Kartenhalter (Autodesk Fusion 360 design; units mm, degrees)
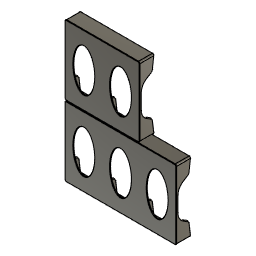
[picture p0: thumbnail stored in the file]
sketch "Skizze1" plane through (0, 0, 0) normal (0, 1, 0) x axis (1, 0, 0)
  line L1 (52, -2) -> (2, -2)
  line L2 (52, -97) -> (52, -2)
  line L3 (2, -97) -> (52, -97)
  line L4 (2, -2) -> (2, -97)
  line L5 (104, -2) -> (54, -2)
  line L6 (104, -97) -> (104, -2)
  line L7 (54, -97) -> (104, -97)
  line L8 (54, -2) -> (54, -97)
  line L9 (156, -2) -> (106, -2)
  line L10 (156, -97) -> (156, -2)
  line L11 (106, -97) -> (156, -97)
  line L12 (106, -2) -> (106, -97)
  line L13 (0, -99) -> (158, -99)
  line L14 (0, 0) -> (0, -99)
  line L15 (158, 0) -> (0, 0)
  line L16 (158, -99) -> (158, 0)
  curve K1 (12, -49.5) -> (42, -49.5)
  curve K2 (27, -79.5) -> (27, -19.5)
  curve K3 (64, -49.5) -> (94, -49.5)
  curve K4 (79, -79.5) -> (79, -19.5)
  curve K5 (116, -49.5) -> (146, -49.5)
  curve K6 (131, -79.5) -> (131, -19.5)
  line L17 (52, -102) -> (2, -102)
  line L18 (79, -179.5) -> (79, -119.5)
  line L19 (104, -197) -> (104, -102)
  line L20 (52, -197) -> (52, -102)
  line L21 (54, -197) -> (104, -197)
  line L22 (2, -197) -> (52, -197)
  line L23 (104, -102) -> (54, -102)
  line L24 (27, -179.5) -> (27, -119.5)
  line L25 (2, -102) -> (2, -197)
  line L26 (54, -102) -> (54, -197)
  line L27 (0, -100) -> (0, -199)
  line L28 (64, -149.5) -> (94, -149.5)
  curve K7 (12, -149.5) -> (42, -149.5)
  curve K8 (27, -179.5) -> (27, -119.5)
  line L29 (12, -149.5) -> (42, -149.5)
  curve K9 (64, -149.5) -> (94, -149.5)
  curve K10 (79, -179.5) -> (79, -119.5)
  line L30 (0, -199) -> (106, -199)
  line L31 (106, -100) -> (0, -100)
  line L32 (106, -100) -> (106, -199)
  closed curve K11 centre (27, -49.5)
  closed curve K12 centre (79, -49.5)
  closed curve K13 centre (131, -49.5)
  closed curve K14 centre (27, -149.5)
  closed curve K15 centre (79, -149.5)
  point P1 (0, 0)
  point P15 (0, 0)
  point P19 (42, -49.5)
  point P20 (12, -49.5)
  point P21 (27, -19.5)
  point P22 (27, -79.5)
  point P24 (94, -49.5)
  point P25 (64, -49.5)
  point P26 (79, -19.5)
  point P27 (79, -79.5)
  point P29 (146, -49.5)
  point P30 (116, -49.5)
  point P31 (131, -19.5)
  point P32 (131, -79.5)
  point P34 (42, -149.5)
  point P35 (12, -149.5)
  point P41 (27, -119.5)
  point P44 (27, -179.5)
  point P43 (94, -149.5)
  point P51 (64, -149.5)
  point P52 (79, -119.5)
  point P50 (79, -179.5)
  point P2 (2, -2)
  point P3 (52, -2)
  point P5 (2, -97)
  point P6 (54, -2)
  point P7 (104, -2)
  point P9 (54, -97)
  point P10 (106, -2)
  point P11 (156, -2)
  point P13 (106, -97)
  point P28 (131, -49.5)
  point P23 (79, -49.5)
  point P18 (27, -49.5)
  point P36 (2, -102)
  point P38 (52, -102)
  point P39 (2, -197)
  point P46 (104, -102)
  point P49 (54, -102)
  point P47 (54, -197)
  point P42 (79, -149.5)
  point P33 (27, -149.5)
  horizontal L1
  vertical L2
  horizontal L3
  vertical L4
  horizontal L5
  vertical L6
  horizontal L7
  vertical L8
  horizontal L9
  vertical L10
  horizontal L11
  vertical L12
  horizontal L13
  vertical L14
  horizontal L15
  coincident P1 P15
  perpendicular L13 L16
  perpendicular L10 K1
  coincident K11 P19
  coincident K11 P20
  coincident K11 P21
  coincident K11 P22
  horizontal K3
  coincident K12 P24
  coincident K12 P25
  coincident K12 P26
  coincident K12 P27
  perpendicular L10 K5
  coincident K13 P29
  coincident K13 P30
  coincident K13 P31
  coincident K13 P32
  horizontal L17
  vertical L20
  horizontal L22
  vertical L25
  horizontal L23
  vertical L19
  horizontal L21
  vertical L26
  horizontal L30
  vertical L27
  horizontal L31
  coincident P34 K14
  coincident P35 K14
  coincident P41 K14
  coincident P44 K14
  horizontal L28
  coincident P43 K15
  coincident P51 K15
  coincident P52 K15
  coincident P50 K15
  perpendicular L31 L32
  dimension "d1" distance P2 P3 = 50
  dimension "d2" distance P2 P5 = 95
  dimension "d3" distance P6 P7 = 50
  dimension "d4" distance P6 P9 = 95
  dimension "d5" distance P10 P11 = 50
  dimension "d6" distance P10 P13 = 95
  dimension "d36" distance P11 P28 = 25
  dimension "d39" distance P7 P23 = 25
  dimension "d40" distance P3 P18 = 25
  dimension "d50" = 60
  dimension "d51" = 60
  dimension "d52" = 60
  dimension "d58" distance P36 P38 = 50
  dimension "d59" distance P36 P39 = 95
  dimension "d60" distance P46 P49 = 50
  dimension "d61" distance P47 P49 = 95
  dimension "d63" distance P42 P46 = 25
  dimension "d64" distance P33 P38 = 25
  dimension "d65" = 60
  dimension "d66" = 60
extrude "Extrusion1" new body sketch "Skizze1" profile of L1 L2 L3 L4 L5 L6 L7 L8 L9 L10 L11 L12 L13 L14 L15 L16 K11 K12 K13 L17 L19 L20 L21 L22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 along normal blind 1.4
extrude "Extrusion2" add sketch "Skizze1" profile of L1 L2 L3 L4 L5 L6 L7 L8 L9 L10 L11 L12 L13 L14 L15 L16 L17 L19 L20 L21 L22 L23 L25 L26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 blind 20 from offset 1.4
sketch "Skizze2" plane through (0, 0, 0) normal (1, 0, 0) x axis (0, 1, 0)
  line L1 (21.4, 0) -> (0, 0)
  line L2 (21.4, 99) -> (0, 99)
  line L3 (10.5375, 73.1629) -> (16.7699, 76.9989)
  line L4 (21.4, 99) -> (19.1106, 80.6384)
  line L5 (21.4, 0) -> (21.4, 99)
  line L6 (8.1045, 49.5) -> (-31.8955, 49.5)
  line L7 (21.4, 0) -> (19.1106, 18.3616)
  line L8 (10.5375, 25.8371) -> (16.7699, 22.0011)
  line L9 (3.4, 49.5) -> (3.4, 60.3887)
  line L10 (3.4, 49.5) -> (3.4, 38.6113)
  line L11 (0, 0) -> (0, 99)
  line L12 (10.5375, 125.8371) -> (16.7699, 122.0011)
  line L13 (3.4, 149.5) -> (3.4, 138.6113)
  line L14 (21.4, 100) -> (21.4, 199)
  line L15 (3.4, 149.5) -> (3.4, 160.3887)
  line L16 (21.4, 199) -> (19.1106, 180.6384)
  line L17 (8.1045, 149.5) -> (-31.8955, 149.5)
  line L18 (10.5375, 173.1629) -> (16.7699, 176.9989)
  line L19 (21.4, 100) -> (19.1106, 118.3616)
  arc A1 centre (14.149, 81.257) radius 5 clockwise from (19.1106, 80.6384) to (16.7699, 76.9989)
  arc A2 centre (14.149, 17.743) radius 5 clockwise from (16.7699, 22.0011) to (19.1106, 18.3616)
  arc A3 centre (18.4, 60.3887) radius 15 clockwise from (3.4, 60.3887) to (10.5375, 73.1629)
  arc A4 centre (18.4, 38.6113) radius 15 clockwise from (10.5375, 25.8371) to (3.4, 38.6113)
  arc A5 centre (18.4, 160.3887) radius 15 clockwise from (3.4, 160.3887) to (10.5375, 173.1629)
  arc A6 centre (14.149, 117.743) radius 5 clockwise from (16.7699, 122.0011) to (19.1106, 118.3616)
  arc A7 centre (18.4, 138.6113) radius 15 clockwise from (10.5375, 125.8371) to (3.4, 138.6113)
  arc A8 centre (14.149, 181.257) radius 5 clockwise from (19.1106, 180.6384) to (16.7699, 176.9989)
  point P5 (21.4, 99)
  point P6 (21.4, 99)
  point P10 (21.4, 99)
  point P3 (21.4, 0)
  point P11 (21.4, 0)
  point P15 (21.4, 0)
  point P7 (19.1106, 80.6384)
  point P14 (19.1106, 18.3616)
  point P8 (16.7699, 76.9989)
  point P17 (16.7699, 22.0011)
  point P18 (3.4, 49.5)
  point P19 (3.4, 49.5)
  point P31 (21.4, 100)
  point P34 (21.4, 199)
  point P30 (19.1106, 118.3616)
  point P35 (19.1106, 180.6384)
  point P29 (16.7699, 122.0011)
  point P36 (16.7699, 176.9989)
  point P43 (3.4, 149.5)
  point P42 (3.4, 149.5)
  point P1 (0, 0)
  point P12 (-31.8955, 49.5)
  point P13 (8.1045, 49.5)
  point P26 (-31.8955, 149.5)
  point P28 (8.1045, 149.5)
  coincident P5 P6
  tangent L4 A1
  tangent L3 A1
  coincident P5 P10
  coincident P3 P11
  horizontal L6
  symmetric P6 L6 P15
  symmetric P7 L6 P14
  symmetric P8 L6 P17
  symmetric A1 L6 A2
  coincident L6 P18
  perpendicular L6 L9
  symmetric L6 P18 P19
  tangent L3 A3
  tangent L9 A3
  tangent L10 A4
  tangent L8 A4
  equal A3 A4
  tangent L16 A8
  tangent L18 A8
  horizontal L17
  symmetric P31 P34 L17
  symmetric P30 P35 L17
  symmetric P29 P36 L17
  symmetric L17 A6 A8
  coincident P43 L17
  perpendicular L15 L17
  symmetric P42 P43 L17
  tangent A5 L18
  tangent A5 L15
  tangent L13 A7
  tangent L12 A7
  equal A5 A7
  dimension "d24" radius A1 = 5
  dimension "d48" distance P1 L6 = 49.5
  dimension "d49" distance P12 P13 = 40
  dimension "d55" distance L10 L11 = 3.4
  dimension "d56" radius A3 = 15
  dimension "d67" radius A8 = 5
  dimension "d68" distance P26 P28 = 40
  dimension "d69" radius A5 = 15
extrude "Extrusion3" cut sketch "Skizze2" profile of L3 A1 L5 along normal blind 300
extrude "Extrusion4" cut sketch "Skizze2" profile of L12 A5 L13 L14 L15 L16 A6 L18 A7 L19 A8 along normal blind 300
fillet "Abrundung1" radius 1 1
fillet "Abrundung2" radius 2 2 2
fillet "Abrundung3" radius 0.5 0.5
fillet "Abrundung4" radius 1 1
fillet "Abrundung7" radius 0.6 0.6
fillet "Abrundung8" radius 1 1
named bodies: "Kartenhalter3x", "Kartenhalter2x"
